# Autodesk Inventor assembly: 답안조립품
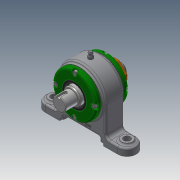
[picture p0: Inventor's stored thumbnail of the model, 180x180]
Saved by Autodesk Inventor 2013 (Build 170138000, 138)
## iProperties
Created: 2019-05
Part Number: 답안조립품
Document SubType Name: Assembly
Designer: user
Author: user
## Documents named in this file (13)
- C:\Users\user\Desktop\490504V1010\답안조립품.iam
- C:\Users\user\Desktop\490504V1010\본체.ipt
- C:\Users\user\Desktop\490504V1010\개스킷.ipt
- C:\Users\user\Desktop\490504V1010\그리스니플 M6.ipt
- 그리스니플  M6.ipt
- C:\Users\user\Desktop\490504V1010\그리스니플개스킷.ipt
- C:\Users\user\Desktop\490504V1010\베어링너트.ipt
- C:\Users\user\Desktop\490504V1010\볼트 M4.ipt
- C:\Users\user\Desktop\490504V1010\앵귤러 볼 베어링 7205.ipt
- C:\Users\user\Desktop\490504V1010\오일 실 28 40 5 B.ipt
- C:\Users\user\Desktop\490504V1010\축.ipt
- C:\Users\user\Desktop\490504V1010\칼라.ipt
- C:\Users\user\Desktop\490504V1010\커버.ipt
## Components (4 placed, 3 different names)
1. 개스킷:1
2. 그리스니플  M6:1
3. 그리스니플개스킷:1
4. 개스킷:2
